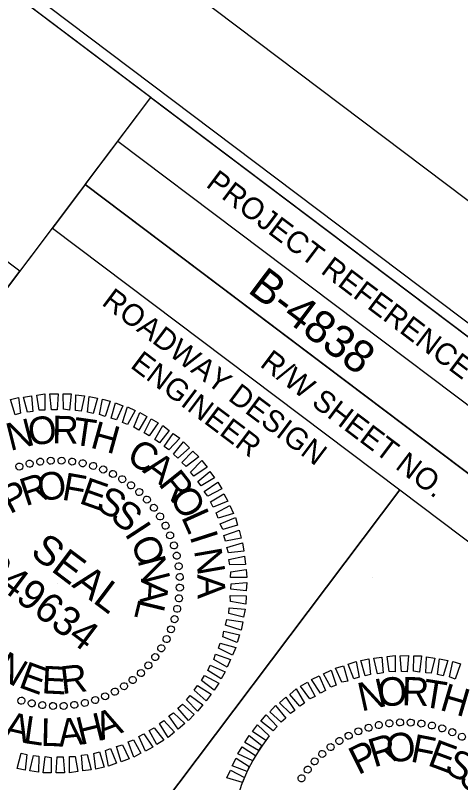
# Model space of a CAD drawing. Extents: x 2296955 to 2298159, y 600182 to 601317.
# Drawn here: x 2298027.2 to 2298088.7, y 600681.2 to 600787.1 of the extents above; entities that cross this region are included whole.
import ezdxf

# ---------------------------------------------------------------- set-up
doc = ezdxf.new("R2010")
doc.units = 0
for name, color, linetype in [('Default', 7, 'Continuous'), ('Exist DTM Drainline Cogo Comment', 7, 'Continuous'), ('Exist DTM Drainline Cogo Elevation', 7, 'Continuous'), ('Exist Property Iron Pin Cogo Number', 7, 'Continuous'), ('Exist Roads Curbs Cogo Number', 7, 'Continuous'), ('Exist Roads Curbs Cogo Point CELL', 7, 'Continuous'), ('Exist Roads EOP Cogo Comment', 7, 'Continuous'), ('Exist Roads EOP Cogo Point CELL', 7, 'Continuous'), ('Exist Roads EOP Other Cogo Number', 7, 'Continuous'), ('Exist Roads EOP Other Cogo Point CELL', 7, 'Continuous')]:
    doc.layers.add(name, color=color, linetype=linetype)

# ---------------------------------------------------------------- blocks, each defined once
blk = doc.blocks.new('POINT_DISPLAY')
at = {"layer": 'Default'}
blk.add_line((0, 0), (0, 0), dxfattribs=at)

msp = doc.modelspace()

# ---------------------------------------------------------------- linework, layer by layer
at = {"layer": 'Exist DTM Drainline Cogo Comment'}
msp.add_lwpolyline([(2298148.7, 600700.2), (2297350.15, 601301.97), (2296969.16, 600796.39), (2297767.7, 600194.63)], close=True, dxfattribs=at)
at = {"layer": 'Exist DTM Drainline Cogo Elevation'}
for p, q in [((2298041.39, 600769.72), (2298137.25, 600697.48)), ((2298036.88, 600763.73), (2298032.37, 600757.74)), ((2298036.88, 600763.73), (2298132.74, 600691.49)), ((2298036.88, 600763.73), (2298132.74, 600691.49))]:
    msp.add_line(p, q, dxfattribs=at)
for points in [[(2298141.78, 600703.5), (2297423.02, 601245.14), (2297043.87, 600742.01), (2297762.63, 600200.36)], [(2298045.93, 600775.73), (2298141.78, 600703.5), (2298132.74, 600691.49), (2298036.88, 600763.73)], [(2298032.37, 600757.74), (2298080.31, 600721.61), (2298039.68, 600667.71), (2297991.74, 600703.83)], [(2298080.31, 600721.61), (2298128.23, 600685.5), (2298087.6, 600631.6), (2298039.68, 600667.71)]]:
    msp.add_lwpolyline(points, close=True, dxfattribs=at)
at = {"layer": 'Exist Property Iron Pin Cogo Number'}
msp.add_lwpolyline([(2297342.87, 601088.91), (2297238.27, 600783.77), (2297197.22, 600664.01), (2297465.89, 600461.56), (2297631.65, 600336.65), (2298039.33, 600622.14), (2298039.33, 600622.14), (2297969.72, 600674.6), (2298027.87, 600751.78), (2297428.93, 601203.11)], close=True, dxfattribs=at)
at = {"layer": 'Exist Roads Curbs Cogo Number'}
msp.add_lwpolyline([(2297423.02, 601245.14), (2297043.89, 600742.01), (2297762.65, 600200.36), (2298069.63, 600607.76), (2297973.78, 600679.99), (2298045.93, 600775.73)], close=True, dxfattribs=at)
at = {"layer": 'Exist Roads Curbs Cogo Point CELL'}
msp.add_lwpolyline([(2298158.96, 600709.34), (2297352.03, 601317.42), (2296954.82, 600790.33), (2297761.75, 600182.24)], close=True, dxfattribs=at)
at = {"layer": 'Exist Roads EOP Cogo Comment'}
msp.add_arc((2298080.95, 600672.61), 23.96, 142.9991, 322.9991, dxfattribs=at)
at = {"layer": 'Exist Roads EOP Other Cogo Number'}
for p, q in [((2298076.53, 600709.49), (2298076.53, 600709.49)), ((2298075.99, 600688.81), (2298075.99, 600688.81)), ((2298077.43, 600689.2), (2298077.43, 600689.2)), ((2298078.87, 600689.43), (2298078.87, 600689.43)), ((2298080.37, 600689.57), (2298080.37, 600689.57)), ((2298081.82, 600689.53), (2298081.82, 600689.53)), ((2298083.31, 600689.38), (2298083.31, 600689.38)), ((2298084.77, 600689.13), (2298084.77, 600689.13)), ((2298074.59, 600688.35), (2298074.59, 600688.35)), ((2298086.17, 600688.75), (2298086.17, 600688.75)), ((2298087.55, 600688.22), (2298087.55, 600688.22)), ((2298071.96, 600686.99), (2298071.96, 600686.99)), ((2298073.26, 600687.7), (2298073.26, 600687.7)), ((2298070.73, 600686.14), (2298070.73, 600686.14)), ((2298069.63, 600685.19), (2298069.63, 600685.19)), ((2298068.57, 600684.18), (2298068.57, 600684.18)), ((2298067.6, 600683.05), (2298067.6, 600683.05)), ((2298066.73, 600681.84), (2298066.73, 600681.84))]:
    msp.add_line(p, q, dxfattribs=at)
for points in [[(2298077.26, 600696.26), (2298076.72, 600698.41), (2298077.86, 600698.52), (2298078.02, 600696.37)], [(2298078.86, 600696.54), (2298078.57, 600698.62), (2298079.7, 600698.78), (2298079.66, 600696.53)], [(2298080.57, 600696.56), (2298080.38, 600698.73), (2298081.54, 600698.75), (2298081.34, 600696.53)], [(2298082.2, 600696.6), (2298082.24, 600698.72), (2298083.33, 600698.71), (2298083.04, 600696.47)], [(2298083.9, 600696.38), (2298084, 600698.59), (2298085.16, 600698.39), (2298084.65, 600696.32)], [(2298072.34, 600695.07), (2298071.44, 600697.01), (2298072.55, 600697.36), (2298073.14, 600695.23)], [(2298073.96, 600695.54), (2298073.2, 600697.55), (2298074.3, 600697.95), (2298074.7, 600695.78)], [(2298075.55, 600695.95), (2298074.94, 600698.06), (2298076.06, 600698.31), (2298076.29, 600696.15)], [(2298085.54, 600696.15), (2298085.82, 600698.31), (2298086.94, 600698.06), (2298086.32, 600695.95)], [(2298087.16, 600695.82), (2298087.63, 600697.92), (2298088.68, 600697.63), (2298087.95, 600695.48)], [(2298070.82, 600694.4), (2298069.8, 600696.23), (2298070.83, 600696.76), (2298071.53, 600694.66)], [(2298069.35, 600693.56), (2298068.15, 600695.44), (2298069.18, 600695.97), (2298070.07, 600693.95)], [(2298066.54, 600691.79), (2298065.13, 600693.4), (2298065.99, 600694.15), (2298067.18, 600692.2)], [(2298067.92, 600692.78), (2298066.61, 600694.53), (2298067.59, 600695.1), (2298068.64, 600693.13)], [(2298065.21, 600690.76), (2298063.7, 600692.24), (2298064.58, 600693.01), (2298065.85, 600691.17)], [(2298063.96, 600689.55), (2298062.36, 600691.01), (2298063.16, 600691.85), (2298064.58, 600690.1)], [(2298062.85, 600688.36), (2298061.14, 600689.73), (2298061.86, 600690.58), (2298063.39, 600688.97)], [(2298061.81, 600687.03), (2298060, 600688.27), (2298060.69, 600689.19), (2298062.3, 600687.68)], [(2298060.82, 600685.66), (2298058.91, 600686.77), (2298059.54, 600687.73), (2298061.25, 600686.35)], [(2298060.01, 600684.25), (2298057.97, 600685.19), (2298058.58, 600686.17), (2298060.39, 600684.98)], [(2298059.27, 600682.77), (2298057.19, 600683.54), (2298057.72, 600684.58), (2298059.54, 600683.46)], [(2298058.62, 600681.23), (2298056.43, 600681.91), (2298056.94, 600682.93), (2298058.86, 600681.94)]]:
    msp.add_lwpolyline(points, close=True, dxfattribs=at)
for centre, major_axis in [((2298078.88, 600689.41), (-0.059, 0.482)), ((2298080.36, 600689.53), (-0.017, 0.486)), ((2298081.83, 600689.52), (0.025, 0.485)), ((2298083.3, 600689.38), (0.068, 0.481)), ((2298074.6, 600688.31), (-0.182, 0.451)), ((2298076, 600688.8), (-0.142, 0.465)), ((2298077.43, 600689.17), (-0.101, 0.475)), ((2298084.75, 600689.11), (0.109, 0.474)), ((2298086.18, 600688.71), (0.15, 0.462)), ((2298073.26, 600687.7), (-0.221, 0.433)), ((2298087.56, 600688.19), (0.19, 0.447)), ((2298088.89, 600687.56), (0.228, 0.429)), ((2298071.98, 600686.97), (-0.258, 0.412)), ((2298069.62, 600685.19), (-0.325, 0.361)), ((2298070.76, 600686.13), (-0.292, 0.388)), ((2298068.57, 600684.16), (-0.355, 0.331)), ((2298067.61, 600683.03), (-0.383, 0.299)), ((2298066.75, 600681.83), (-0.408, 0.265))]:
    msp.add_ellipse(centre, major_axis=major_axis, ratio=0.999708, dxfattribs=at)
at = {"layer": 'Exist Roads EOP Other Cogo Point CELL'}
for points in [[(2298027.21, 600731.96), (2298026.57, 600734.09), (2298027.69, 600734.34), (2298027.97, 600732.19)], [(2298028.92, 600732.32), (2298028.35, 600734.43), (2298029.49, 600734.59), (2298029.67, 600732.43)], [(2298030.54, 600732.62), (2298030.2, 600734.69), (2298031.33, 600734.85), (2298031.33, 600732.61)], [(2298032.22, 600732.66), (2298032.01, 600734.85), (2298033.16, 600734.87), (2298033.01, 600732.65)], [(2298033.87, 600732.73), (2298033.86, 600734.85), (2298034.97, 600734.86), (2298034.71, 600732.6)], [(2298035.56, 600732.55), (2298035.61, 600734.75), (2298036.79, 600734.58), (2298036.32, 600732.49)], [(2298037.21, 600732.33), (2298037.45, 600734.51), (2298038.57, 600734.26), (2298038, 600732.15)], [(2298038.84, 600732.03), (2298039.29, 600734.14), (2298040.32, 600733.87), (2298039.63, 600731.73)], [(2298040.48, 600731.51), (2298041.05, 600733.61), (2298042.07, 600733.23), (2298041.19, 600731.27)], [(2298042.06, 600730.91), (2298042.74, 600733.06), (2298043.8, 600732.56), (2298042.73, 600730.62)], [(2298043.6, 600730.26), (2298044.42, 600732.3), (2298045.39, 600731.74), (2298044.3, 600729.85)], [(2298045.03, 600729.47), (2298045.99, 600731.42), (2298046.98, 600730.88), (2298045.74, 600729.07)], [(2298046.48, 600728.59), (2298047.61, 600730.49), (2298048.5, 600729.82), (2298047.13, 600728.11)], [(2298047.78, 600727.62), (2298049.04, 600729.41), (2298049.93, 600728.74), (2298048.42, 600727.13)], [(2298049.08, 600726.55), (2298050.48, 600728.24), (2298051.27, 600727.43), (2298049.67, 600725.98)], [(2298050.23, 600725.38), (2298051.75, 600726.95), (2298052.56, 600726.17), (2298050.82, 600724.82)], [(2298051.41, 600724.08), (2298052.97, 600725.65), (2298053.74, 600724.77), (2298051.87, 600723.52)], [(2298052.46, 600722.78), (2298054.09, 600724.17), (2298054.75, 600723.29), (2298052.88, 600722.16)], [(2298053.32, 600721.41), (2298055.2, 600722.66), (2298055.74, 600721.75), (2298053.83, 600720.73)], [(2298054.18, 600719.96), (2298056.04, 600721.09), (2298056.6, 600720.08), (2298054.57, 600719.24)], [(2298054.97, 600718.43), (2298056.85, 600719.47), (2298057.34, 600718.38), (2298055.24, 600717.72)], [(2298055.52, 600716.92), (2298057.62, 600717.79), (2298057.91, 600716.73), (2298055.87, 600716.15)], [(2298056.04, 600715.3), (2298058.13, 600716.06), (2298058.43, 600714.94), (2298056.27, 600714.54)], [(2298056.46, 600713.68), (2298058.61, 600714.29), (2298058.77, 600713.16), (2298056.69, 600712.91)], [(2298056.74, 600712.03), (2298058.87, 600712.45), (2298059.03, 600711.32), (2298056.85, 600711.27)], [(2298056.98, 600710.33), (2298059.13, 600710.65), (2298059.19, 600709.51), (2298056.97, 600709.53)], [(2298057.04, 600708.67), (2298059.21, 600708.86), (2298059.13, 600707.69), (2298056.98, 600707.92)], [(2298056.91, 600707.04), (2298059.13, 600707.01), (2298059.05, 600705.85), (2298056.93, 600706.22)], [(2298056.77, 600705.33), (2298058.98, 600705.18), (2298058.73, 600704.06), (2298056.7, 600704.58)], [(2298056.46, 600703.75), (2298058.65, 600703.4), (2298058.4, 600702.28), (2298056.28, 600702.95)], [(2298056.03, 600702.12), (2298058.2, 600701.63), (2298057.89, 600700.55), (2298055.88, 600701.35)], [(2298055.52, 600700.48), (2298057.7, 600699.85), (2298057.22, 600698.82), (2298055.28, 600699.77)], [(2298054.87, 600698.94), (2298056.97, 600698.2), (2298056.47, 600697.14), (2298054.63, 600698.23)], [(2298054.16, 600697.45), (2298056.22, 600696.53), (2298055.64, 600695.53), (2298053.81, 600696.7)], [(2298053.37, 600696.01), (2298055.33, 600694.96), (2298054.69, 600694), (2298052.94, 600695.32)], [(2298052.41, 600694.62), (2298054.27, 600693.43), (2298053.58, 600692.52), (2298051.93, 600693.97)], [(2298051.4, 600693.27), (2298053.15, 600691.95), (2298052.4, 600691.08), (2298050.86, 600692.67)], [(2298050.31, 600692.06), (2298051.94, 600690.62), (2298051.14, 600689.79), (2298049.69, 600691.51)], [(2298049.06, 600690.85), (2298050.62, 600689.38), (2298049.74, 600688.6), (2298048.45, 600690.42)], [(2298047.76, 600689.8), (2298049.22, 600688.19), (2298048.36, 600687.45), (2298047.15, 600689.37)], [(2298044.98, 600687.96), (2298046.21, 600686.11), (2298045.2, 600685.56), (2298044.27, 600687.57)], [(2298046.41, 600688.79), (2298047.74, 600687.07), (2298046.78, 600686.48), (2298045.72, 600688.42)], [(2298043.54, 600687.11), (2298044.59, 600685.3), (2298043.58, 600684.75), (2298042.83, 600686.84)], [(2298040.4, 600685.92), (2298041.21, 600683.91), (2298040.11, 600683.52), (2298039.69, 600685.65)], [(2298042.02, 600686.43), (2298042.96, 600684.49), (2298041.86, 600684.1), (2298041.23, 600686.23)], [(2298028.85, 600685.11), (2298028.6, 600682.93), (2298027.48, 600683.19), (2298028.05, 600685.29)], [(2298030.5, 600684.89), (2298030.44, 600682.69), (2298029.26, 600682.86), (2298029.74, 600684.95)], [(2298032.18, 600684.71), (2298032.19, 600682.59), (2298031.08, 600682.58), (2298031.35, 600684.84)], [(2298033.84, 600684.78), (2298034.05, 600682.59), (2298032.89, 600682.57), (2298033.04, 600684.79)], [(2298035.52, 600684.82), (2298035.86, 600682.75), (2298034.72, 600682.59), (2298034.72, 600684.83)], [(2298037.14, 600685.12), (2298037.7, 600683.01), (2298036.57, 600682.85), (2298036.38, 600685.02)], [(2298038.85, 600685.48), (2298039.49, 600683.36), (2298038.36, 600683.1), (2298038.09, 600685.26)]]:
    msp.add_lwpolyline(points, close=True, dxfattribs=at)
for centre, major_axis in [((2298030.67, 600725.5), (-0.068, 0.481)), ((2298032.14, 600725.64), (-0.025, 0.485)), ((2298033.62, 600725.65), (0.017, 0.486)), ((2298035.09, 600725.53), (0.059, 0.482)), ((2298027.8, 600724.83), (-0.15, 0.462)), ((2298029.22, 600725.23), (-0.109, 0.474)), ((2298036.55, 600725.29), (0.101, 0.475)), ((2298037.98, 600724.92), (0.142, 0.465)), ((2298039.37, 600724.43), (0.182, 0.451)), ((2298040.72, 600723.81), (0.221, 0.433)), ((2298042, 600723.09), (0.258, 0.412)), ((2298043.22, 600722.25), (0.293, 0.388)), ((2298044.36, 600721.31), (0.325, 0.361)), ((2298045.41, 600720.28), (0.356, 0.332)), ((2298046.37, 600719.15), (0.383, 0.299)), ((2298047.23, 600717.95), (0.408, 0.265)), ((2298047.98, 600716.68), (0.429, 0.228)), ((2298048.61, 600715.34), (0.447, 0.19)), ((2298049.13, 600713.96), (0.462, 0.15)), ((2298049.53, 600712.54), (0.474, 0.109)), ((2298049.8, 600711.08), (0.481, 0.068)), ((2298049.94, 600709.61), (0.485, 0.025)), ((2298049.95, 600708.14), (0.486, -0.017)), ((2298049.83, 600706.66), (0.482, -0.059)), ((2298049.59, 600705.21), (0.475, -0.101)), ((2298049.22, 600703.78), (0.465, -0.142)), ((2298048.73, 600702.38), (0.451, -0.182)), ((2298048.12, 600701.04), (0.433, -0.221)), ((2298047.39, 600699.76), (0.412, -0.258)), ((2298046.55, 600698.54), (0.388, -0.293)), ((2298045.61, 600697.4), (0.361, -0.325)), ((2298044.58, 600696.34), (0.332, -0.356)), ((2298043.45, 600695.38), (0.299, -0.383)), ((2298040.98, 600693.78), (0.228, -0.429)), ((2298042.25, 600694.53), (0.265, -0.408)), ((2298028.08, 600692.54), (-0.142, -0.465)), ((2298038.26, 600692.62), (0.15, -0.462)), ((2298039.64, 600693.14), (0.19, -0.447)), ((2298029.51, 600692.17), (-0.101, -0.475)), ((2298030.96, 600691.92), (-0.059, -0.482)), ((2298032.44, 600691.81), (-0.017, -0.486)), ((2298033.91, 600691.82), (0.025, -0.485)), ((2298035.38, 600691.96), (0.068, -0.481)), ((2298036.84, 600692.23), (0.109, -0.474))]:
    msp.add_ellipse(centre, major_axis=major_axis, ratio=0.999708, dxfattribs=at)

# ---------------------------------------------------------------- block references
at = {"layer": 'Exist Roads EOP Other Cogo Point CELL', "xscale": 41.411959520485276, "yscale": 41.411959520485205, "rotation": -37.000428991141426}
for p in [(2298027.8, 600724.83), (2298029.21, 600725.25), (2298030.67, 600725.5), (2298032.14, 600725.66), (2298033.61, 600725.65), (2298035.1, 600725.55), (2298036.56, 600725.29), (2298037.98, 600724.94), (2298039.38, 600724.44), (2298040.72, 600723.81), (2298042, 600723.09), (2298043.23, 600722.25), (2298044.37, 600721.31), (2298045.41, 600720.27), (2298046.39, 600719.16), (2298047.25, 600717.95), (2298047.99, 600716.68), (2298048.63, 600715.35), (2298049.14, 600713.95), (2298049.56, 600712.54), (2298049.81, 600711.08), (2298049.97, 600709.61), (2298033.03, 600708.72), (2298049.96, 600708.14), (2298049.85, 600706.65), (2298049.6, 600705.19), (2298049.25, 600703.77), (2298048.74, 600702.37), (2298047.4, 600699.75), (2298046.56, 600698.52), (2298045.61, 600697.38), (2298044.58, 600696.34), (2298043.46, 600695.36), (2298042.26, 600694.49), (2298039.66, 600693.12), (2298040.99, 600693.76), (2298028.08, 600692.5), (2298029.5, 600692.15), (2298036.85, 600692.19), (2298038.26, 600692.61), (2298030.96, 600691.89), (2298032.44, 600691.79), (2298033.91, 600691.78), (2298035.39, 600691.94)]:
    msp.add_blockref('POINT_DISPLAY', p, dxfattribs=at)

# ---------------------------------------------------------------- texts
at = {"layer": 'Exist DTM Drainline Cogo Elevation'}
for s, height, p in [('PROJECT REFERENCE NO.', 3.0001, (2298053.42, 600763.55)), ('ROADWAY DESIGN', 3.0001, (2298039.03, 600747.24)), ('ENGINEER', 3, (2298042.98, 600738.58)), ('R/W SHEET NO.', 3.0001, (2298060.87, 600738.74))]:
    msp.add_text(s, height=height, rotation=322.9991, dxfattribs=at).set_placement(p)
at = {"layer": 'Exist Roads EOP Cogo Point CELL'}
msp.add_text('B-4838', height=4.5, rotation=322.9991, dxfattribs=at).set_placement((2298059.17, 600748.98))
at = {"layer": 'Exist Roads EOP Other Cogo Number'}
for s, height, rotation, p in [('N', 3.93, 12.4226, (2298075.01, 600691.03)), ('O', 3.93, 5.2209, (2298077.43, 600691.66)), ('R', 3.91, 358.0196, (2298080.54, 600691.93)), ('T', 3.88, 350.8189, (2298083.27, 600691.74)), ('H', 3.85, 343.6186, (2298085.69, 600691.3)), ('R', 3.93, 17.0388, (2298076.74, 600683.3)), ('O', 3.93, 7.6804, (2298078.68, 600683.91)), ('F', 3.88, 348.9662, (2298081.66, 600684.16)), ('P', 3.9, 26.398, (2298074.58, 600682.22)), ('E', 3.84, 339.6102, (2298084, 600683.67)), ('S', 3.81, 330.2547, (2298086.28, 600682.83)), ('S', 3.81, 320.8995, (2298088.24, 600681.4))]:
    msp.add_text(s, height=height, rotation=rotation, dxfattribs=at).set_placement(p)
at = {"layer": 'Exist Roads EOP Other Cogo Point CELL'}
for s, height, rotation, p in [('N', 3.81, 14.16, (2298026.53, 600726.97)), ('O', 3.81, 6.2213, (2298029.19, 600727.73)), ('R', 3.81, 359.0201, (2298032.29, 600728.04)), ('T', 3.81, 351.8193, (2298035.01, 600727.9)), ('H', 3.81, 344.619, (2298037.45, 600727.49)), ('C', 3.81, 330.2194, (2298042.4, 600725.58)), ('A', 3.81, 323.0199, (2298044.68, 600724.16)), ('R', 3.81, 18.0392, (2298028.65, 600719.34)), ('O', 3.81, 8.6808, (2298030.59, 600720)), ('F', 3.81, 349.9666, (2298033.54, 600720.29)), ('R', 3.81, 308.6207, (2298046.9, 600722.4)), ('P', 3.81, 27.3985, (2298026.49, 600718.22)), ('E', 3.81, 340.6106, (2298035.9, 600719.83)), ('S', 3.81, 331.2552, (2298038.18, 600719.04)), ('O', 3.81, 301.4207, (2298048.42, 600720.66)), ('S', 3.81, 321.9, (2298040.16, 600717.63)), ('L', 3.81, 294.2204, (2298050.09, 600717.88)), ('I', 3.81, 303.1892, (2298042.24, 600715.56)), ('SEAL', 4.05, 322.9996, (2298029.15, 600712.7)), ('I', 3.81, 287.7801, (2298051.28, 600715.22)), ('O', 3.81, 293.8331, (2298043.06, 600714.34)), ('N', 3.81, 279.8185, (2298051.89, 600713.27)), ('049634', 4.051, 322.9996, (2298022.3, 600710.08)), ('N', 3.81, 284.4762, (2298044.09, 600711.96)), ('A', 3.81, 265.7598, (2298044.62, 600709.4)), ('A', 3.81, 271.0617, (2298052.37, 600709.96)), ('L', 3.81, 256.4004, (2298044.3, 600706.73)), ('N', 3.81, 329.056, (2298024.2, 600696.22)), ('E', 3.81, 339.9664, (2298027.54, 600694.44)), ('E', 3.81, 357.1237, (2298030.82, 600693.56)), ('R', 3.81, 6.481, (2298033.69, 600693.44)), ('A', 3.81, 20.8779, (2298039.14, 600687.01)), ('A', 3.81, 346.983, (2298025.47, 600687.41)), ('L', 3.81, 351.7279, (2298028.21, 600686.72)), ('L', 3.81, 358.6931, (2298030.72, 600686.3)), ('A', 3.81, 5.8784, (2298033.31, 600686.17)), ('H', 3.81, 13.6827, (2298036.21, 600686.38))]:
    msp.add_text(s, height=height, rotation=rotation, dxfattribs=at).set_placement(p)

doc.saveas('drawing.dxf')
